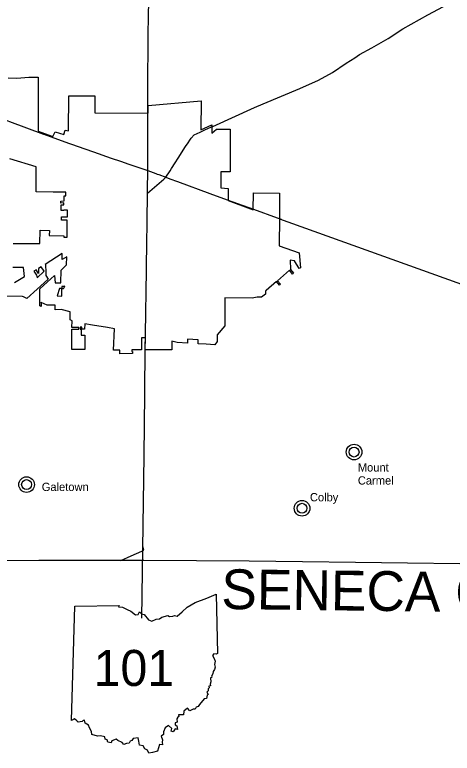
# Model space of a CAD drawing. Extents: x 0 to 798, y 0 to 440.
# Drawn here: x 452.7 to 507.6, y 103 to 195.7 of the extents above; entities that cross this region are included whole.
import ezdxf

# ---------------------------------------------------------------- set-up
doc = ezdxf.new("R2010")
doc.units = 0
for name, color, linetype in [('DV_X_Corp_Line', 7, 'Continuous'), ('GM_X_Adjacent_County_Text', 7, 'Continuous'), ('GM_X_County', 7, 'Continuous'), ('GM_X_State_Route', 7, 'Continuous'), ('GM_X_US_Route', 7, 'Continuous'), ('PV_P_Text', 7, 'Continuous')]:
    doc.layers.add(name, color=color, linetype=linetype)

msp = doc.modelspace()

# ---------------------------------------------------------------- linework, layer by layer
at = {"layer": 'DV_X_Corp_Line'}
for points in [[(451.882, 187.777), (452.994, 187.738), (454.478, 187.842), (455.663, 187.863), (455.663, 181.066), (457.485, 180.419), (457.813, 180.973), (458.892, 180.643), (459.042, 181.185), (459.475, 181.12), (459.504, 185.491), (462.775, 185.49), (462.791, 183.36), (469.48, 183.316), (469.48, 184.304), (476.119, 184.9), (476.077, 181.222), (477.469, 181.872), (477.47, 180.811), (478.027, 181.332), (479.748, 181.332), (479.749, 175.96), (478.593, 175.959), (478.594, 173.963), (479.487, 173.87), (479.487, 172.378), (482.658, 171.213), (482.697, 173.346), (485.961, 173.29), (485.961, 170.384), (485.962, 170.066), (485.906, 166.853), (485.904, 166.685), (488.416, 165.784), (488.574, 163.918), (488.432, 163.816), (487.847, 164.772), (487.29, 164.88), (487.311, 163.702), (487.714, 163.234), (487.587, 163.131), (487.197, 163.604), (485.687, 162.291), (486.057, 161.85), (485.946, 161.753), (485.576, 162.194), (484.289, 161.074), (484.179, 161.039), (484.179, 160.616), (483.686, 160.244), (483.163, 160.235), (482.522, 160.097), (479.067, 160.136), (479.067, 156.621), (478.138, 155.514), (478.138, 154.642), (477.835, 154.261), (476.746, 154.326), (475.729, 154.388), (475.729, 154.889), (474.399, 154.958), (474.399, 154.47), (473.112, 154.549), (472.437, 154.707), (472.431, 153.634), (469.101, 153.633), (469.129, 155.137), (468.629, 155.137), (468.629, 153.633), (467.429, 153.612), (467.429, 153.395), (467.484, 153.396), (467.484, 153.158), (465.904, 153.131), (465.904, 153.562), (465.132, 153.572), (465.226, 156.26), (464.351, 156.418), (462.461, 156.721), (461.506, 156.88), (461.493, 156.214), (461.143, 156.217), (461.141, 156.442), (460.917, 156.44), (460.917, 156.209), (461.067, 156.211), (461.067, 155.461), (461.529, 155.469), (461.529, 153.663), (459.882, 153.663), (459.904, 156.214), (460.764, 156.206), (460.764, 156.439), (459.905, 156.433), (459.922, 157.277), (459.698, 157.368), (459.681, 158.381), (458.568, 158.686), (457.776, 158.656), (457.788, 159.216), (456.8, 159.204), (456.038, 159.575), (456.03, 159.581), (456.035, 159.063), (455.869, 159.146), (455.877, 160.321), (455.883, 161.255), (457.728, 162.949), (457.776, 162.023), (458.525, 162.039), (458.553, 163.627), (459.216, 164.268), (459.246, 165.31), (458.686, 164.96), (458.686, 165.722), (456.541, 164.344), (456.565, 164.306), (456.615, 163.35), (456.643, 162.95), (456.914, 162.5), (455.542, 161.22), (454.249, 160.051), (454.007, 160.187), (453.81, 160.274), (453.711, 160.291), (449.932, 160.373)], [(452.536, 166.978), (455.887, 166.956), (455.911, 168.634), (457.066, 168.618), (457.057, 167.953), (458.871, 167.931), (458.871, 167.743), (459.291, 167.749), (459.32, 169.905), (458.611, 169.911), (458.611, 170.324), (459.328, 170.318), (459.339, 171.147), (458.884, 171.139), (458.884, 171.106), (458.542, 171.094), (458.542, 171.827), (458.885, 171.833), (458.885, 172.053), (458.5, 172.047), (458.5, 172.297), (458.935, 172.305), (458.935, 172.962), (459.114, 172.965), (459.114, 173.398), (458.44, 173.407), (457.526, 173.42), (455.401, 173.44), (455.401, 176.586), (452.122, 177.618)], [(452.674, 162.057), (453.945, 162.826), (453.814, 163.944), (452.493, 163.962)]]:
    msp.add_lwpolyline(points, dxfattribs=at)
for points in [[(455.542, 162.661), (456.414, 163.475), (456.026, 164.05), (455.701, 163.847), (455.701, 163.182), (455.411, 163.665), (455.116, 163.48), (455.433, 162.97)], [(458.624, 161.328), (458.803, 161.327), (458.854, 161.286), (458.993, 161.591), (458.898, 161.566), (458.625, 161.572)], [(458.624, 161.328), (458.327, 161.329), (458.062, 160.401), (458.619, 160.349)]]:
    msp.add_lwpolyline(points, close=True, dxfattribs=at)
for centre, radius in [((495.3, 140.78), 0.982), ((495.3, 140.78), 0.623), ((454.208, 136.692), 0.982), ((454.208, 136.692), 0.623), ((488.771, 133.716), 0.982), ((488.771, 133.716), 0.623)]:
    msp.add_circle(centre, radius, dxfattribs=at)
at = {"layer": 'GM_X_County'}
msp.add_lwpolyline([(508.594, 126.756), (502.016, 126.819), (495.464, 126.891), (488.828, 126.994), (482.151, 127.087), (468.912, 127.146), (466.018, 127.172), (455.728, 127.162), (448.563, 127.127)], dxfattribs=at)
at = {"layer": 'GM_X_State_Route'}
msp.add_line((485.962, 170.066), (528.55, 154.711), dxfattribs=at)
for points in [[(469.488, 195.343), (469.722, 206.488), (469.906, 206.741), (469.984, 206.905), (470.105, 213.119), (470.31, 219.731), (470.468, 230.182), (470.519, 233.299), (470.702, 246.178), (471.047, 266.057)], [(477.432, 181.6), (477.573, 181.663), (482.826, 184.036), (483.911, 184.49), (488.484, 186.438), (490.854, 187.494), (492.616, 188.432), (494.32, 189.607), (495.402, 190.291), (495.991, 190.685), (497.538, 191.526), (499.598, 192.696), (501.418, 193.914), (504.554, 195.674), (507.169, 197.074)], [(469.43, 186.048), (469.445, 193.329), (469.488, 195.343)], [(469.426, 184.327), (469.43, 186.048)], [(469.424, 183.4), (469.426, 184.327), (469.426, 184.327)], [(469.417, 180.091), (469.424, 183.4), (469.424, 183.4)], [(471.669, 175.294), (472.21, 176.075), (472.405, 176.382), (472.856, 177.096), (473.232, 177.689), (474.162, 179.129), (474.473, 179.612), (474.708, 179.961), (474.882, 180.199), (475.019, 180.373), (475.08, 180.443), (475.192, 180.557), (475.242, 180.597), (475.993, 180.946), (475.995, 180.947)], [(475.995, 180.947), (476.589, 181.223), (477.333, 181.556), (477.429, 181.599), (477.432, 181.6)], [(469.408, 176.12), (469.414, 178.775), (469.417, 180.091), (469.417, 180.091)], [(469.393, 173.29), (469.395, 173.674), (469.396, 173.941), (469.4, 174.598), (469.403, 175.2), (469.408, 176.12)], [(471.482, 175.107), (471.669, 175.294)], [(469.393, 173.29), (470.564, 174.308), (471.436, 175.06), (471.482, 175.107), (471.482, 175.107)], [(469.357, 170.848), (469.36, 171.013), (469.374, 172.006), (469.38, 172.394), (469.39, 173.006), (469.393, 173.29)], [(469.277, 165.52), (469.278, 165.589), (469.29, 166.397), (469.297, 166.865), (469.309, 167.633), (469.311, 167.799), (469.325, 168.738), (469.34, 169.682), (469.356, 170.804), (469.357, 170.848)], [(469.121, 155.124), (469.129, 155.615), (469.248, 163.597), (469.253, 163.897), (469.262, 164.521), (469.276, 165.444), (469.277, 165.52)], [(469.102, 153.741), (469.107, 154.143), (469.121, 155.124)], [(469.031, 148.108), (469.032, 148.24), (469.102, 153.741), (469.102, 153.741)], [(468.669, 119.905), (468.947, 140.32), (469.031, 148.108)], [(468.784, 128.398), (468.917, 128.459), (468.792, 128.927), (468.793, 128.97)], [(466.018, 127.172), (467.315, 127.743), (468.662, 128.342), (468.784, 128.398)]]:
    msp.add_lwpolyline(points, dxfattribs=at)
at = {"layer": 'GM_X_US_Route'}
for points in [[(449.904, 183.153), (449.949, 183.135), (452.078, 182.278), (456.343, 180.712)], [(456.343, 180.712), (456.358, 180.706), (459.451, 179.571), (459.826, 179.439), (459.826, 179.439)], [(459.826, 179.439), (463.297, 178.223), (464.116, 177.936), (464.945, 177.645), (465.869, 177.33), (466.722, 177.038), (466.795, 177.013), (467.669, 176.714), (468.051, 176.584), (469.408, 176.12)], [(469.408, 176.12), (470.438, 175.743), (470.611, 175.68), (470.795, 175.613), (471.669, 175.294)], [(471.669, 175.294), (472.199, 175.098), (473.162, 174.742), (473.167, 174.74)], [(473.167, 174.74), (477.203, 173.248), (479.395, 172.452), (482.665, 171.265), (485.639, 170.185), (485.656, 170.179)], [(485.656, 170.179), (486.139, 170.004), (486.154, 169.998)]]:
    msp.add_lwpolyline(points, dxfattribs=at)
at = {"layer": 'PV_P_Text'}
msp.add_line((459.852, 107.065), (460.254, 121.427), dxfattribs=at)
msp.add_line((459.852, 107.065), (460.254, 121.427), dxfattribs=at)
for points in [[(460.254, 121.427), (465.826, 121.521), (465.739, 121.347), (466.265, 121.311), (466.824, 121.004), (467.296, 120.81), (467.874, 120.353), (468.22, 120.359), (468.366, 120.733), (468.631, 120.444), (468.945, 120.392), (469.488, 119.705), (469.936, 119.556), (470.473, 119.792), (470.875, 119.83), (471.168, 120.063), (471.933, 120.262), (472.146, 120.143), (472.551, 120.167), (472.755, 120.255), (473.108, 120.177), (473.73, 120.699), (474.37, 121.315), (475.354, 121.896), (476.824, 122.446), (477.986, 122.938), (478.154, 115.485)], [(460.254, 121.427), (465.826, 121.521), (465.739, 121.347), (466.265, 121.311), (466.824, 121.004), (467.296, 120.81), (467.874, 120.353), (468.22, 120.359), (468.366, 120.733), (468.631, 120.444), (468.945, 120.392), (469.488, 119.705), (469.936, 119.556), (470.473, 119.792), (470.875, 119.83), (471.168, 120.063), (471.933, 120.262), (472.146, 120.143), (472.551, 120.167), (472.755, 120.255), (473.108, 120.177), (473.73, 120.699), (474.37, 121.315), (475.354, 121.896), (476.824, 122.446), (477.986, 122.938), (478.154, 115.485)], [(478.154, 115.485), (477.983, 115.38), (477.715, 115.43), (477.536, 115.22), (477.758, 114.872), (477.863, 114.503), (477.77, 114.097), (477.862, 113.762), (477.799, 113.482), (477.632, 113.203), (477.574, 112.937), (477.431, 112.656), (477.443, 112.5), (477.307, 112.375), (477.331, 111.909), (477.263, 111.651), (477.286, 111.428), (477.066, 111.37), (477.116, 111.185), (476.976, 111.043), (477.006, 110.798), (476.847, 110.642), (477.001, 110.33), (476.877, 110.231), (476.774, 109.85), (476.491, 109.773), (475.924, 109.077), (475.724, 108.815), (475.5, 108.749), (475.376, 108.479), (475.099, 108.478), (474.681, 108.291), (474.41, 108.613), (473.936, 108.225), (473.881, 107.777), (473.282, 107.792), (473.305, 107.565), (473.172, 107.499), (473.05, 107.273), (473.12, 106.869), (472.84, 106.767), (472.874, 106.533), (473.054, 106.389), (473.133, 105.942), (472.835, 106.033), (472.591, 105.656), (472.34, 105.744), (472.422, 106.064), (471.997, 106.448), (471.596, 106.14), (471.386, 105.649), (471.384, 105.318), (471.085, 105.118), (471.276, 104.651), (471.241, 104.33), (471.247, 104.024), (470.873, 104.035), (470.647, 103.21)], [(478.154, 115.485), (477.983, 115.38), (477.715, 115.43), (477.536, 115.22), (477.758, 114.872), (477.863, 114.503), (477.77, 114.097), (477.862, 113.762), (477.799, 113.482), (477.632, 113.203), (477.574, 112.937), (477.431, 112.656), (477.443, 112.5), (477.307, 112.375), (477.331, 111.909), (477.263, 111.651), (477.286, 111.428), (477.066, 111.37), (477.116, 111.185), (476.976, 111.043), (477.006, 110.798), (476.847, 110.642), (477.001, 110.33), (476.877, 110.231), (476.774, 109.85), (476.491, 109.773), (475.924, 109.077), (475.724, 108.815), (475.5, 108.749), (475.376, 108.479), (475.099, 108.478), (474.681, 108.291), (474.41, 108.613), (473.936, 108.225), (473.881, 107.777), (473.282, 107.792), (473.305, 107.565), (473.172, 107.499), (473.05, 107.273), (473.12, 106.869), (472.84, 106.767), (472.874, 106.533), (473.054, 106.389), (473.133, 105.942), (472.835, 106.033), (472.591, 105.656), (472.34, 105.744), (472.422, 106.064), (471.997, 106.448), (471.596, 106.14), (471.386, 105.649), (471.384, 105.318), (471.085, 105.118), (471.276, 104.651), (471.241, 104.33), (471.247, 104.024), (470.873, 104.035), (470.647, 103.21)], [(470.647, 103.21), (469.996, 103.053), (469.545, 102.958), (469.386, 103.333), (469.063, 103.53), (468.853, 103.907), (468.389, 103.959), (468.279, 104.476), (468.227, 104.897), (467.594, 104.793), (467.42, 104.536), (467.195, 104.467), (467.064, 104.208), (466.758, 104.187), (466.429, 104.065), (466.214, 104.318), (465.675, 104.573), (465.433, 104.705), (464.927, 104.501), (464.818, 104.259), (464.415, 104.365), (464.321, 104.635), (464.077, 104.716), (464.023, 105.002), (463.502, 105.154), (463.103, 105.094), (462.399, 105.324), (462.357, 105.7), (462.117, 106.159), (461.992, 106.478), (461.547, 106.721), (461.457, 107.099), (461.315, 107.088), (461.185, 106.935), (460.691, 106.864), (460.494, 107.019), (460.217, 107.283), (459.852, 107.065)], [(470.647, 103.21), (469.996, 103.053), (469.545, 102.958), (469.386, 103.333), (469.063, 103.53), (468.853, 103.907), (468.389, 103.959), (468.279, 104.476), (468.227, 104.897), (467.594, 104.793), (467.42, 104.536), (467.195, 104.467), (467.064, 104.208), (466.758, 104.187), (466.429, 104.065), (466.214, 104.318), (465.675, 104.573), (465.433, 104.705), (464.927, 104.501), (464.818, 104.259), (464.415, 104.365), (464.321, 104.635), (464.077, 104.716), (464.023, 105.002), (463.502, 105.154), (463.103, 105.094), (462.399, 105.324), (462.357, 105.7), (462.117, 106.159), (461.992, 106.478), (461.547, 106.721), (461.457, 107.099), (461.315, 107.088), (461.185, 106.935), (460.691, 106.864), (460.494, 107.019), (460.217, 107.283), (459.852, 107.065)]]:
    msp.add_lwpolyline(points, dxfattribs=at)

# ---------------------------------------------------------------- texts
at = {"layer": 'DV_X_Corp_Line'}
for s, p in [('Mount', (495.777, 138.331)), ('Carmel', (495.777, 136.692)), ('Galetown', (456.114, 135.885)), ('Colby', (489.763, 134.589))]:
    msp.add_text(s, height=1.0417, rotation=0.00001, dxfattribs=at).set_placement(p)
at = {"layer": 'GM_X_Adjacent_County_Text'}
msp.add_text('SENECA COUNTY', height=5, rotation=359.30548, dxfattribs=at).set_placement((478.623, 121.073))
at = {"layer": 'PV_P_Text'}
msp.add_text('101', height=4.5281, dxfattribs=at).set_placement((462.624, 111.402))

doc.saveas('drawing.dxf')
